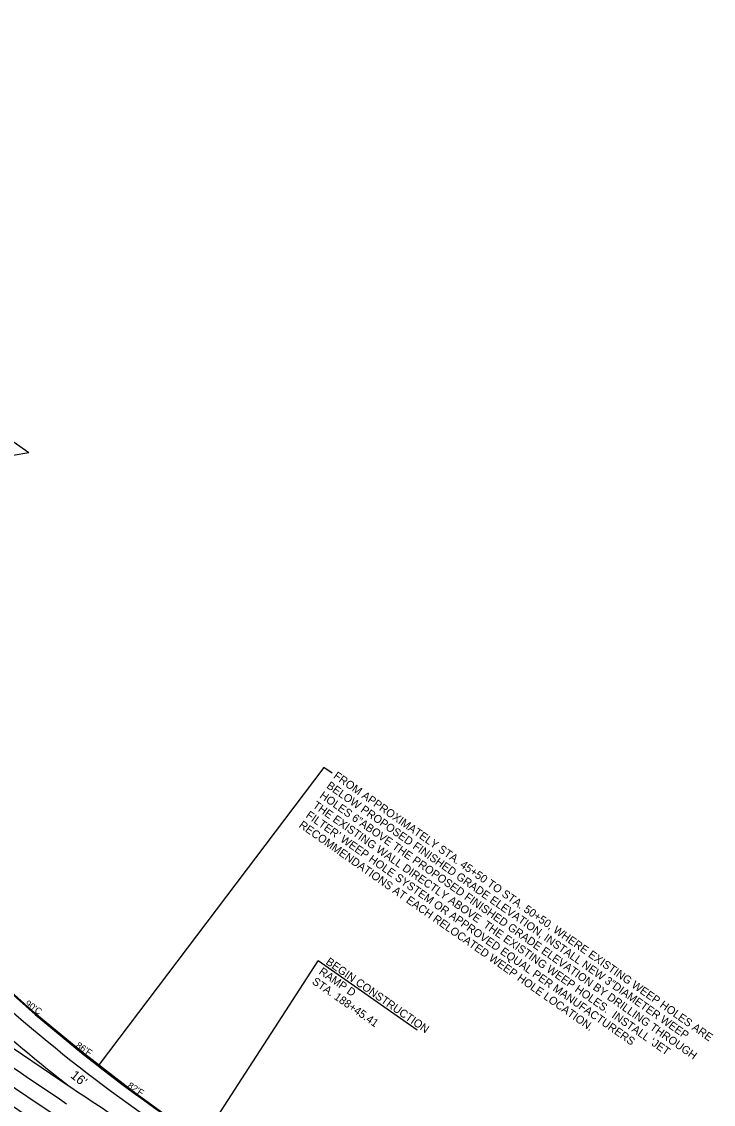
# Model space of a CAD drawing. Extents: x 1966090 to 1975830, y 788086 to 801233.
# Drawn here: x 1972167 to 1972685, y 795066 to 795878 of the extents above; entities that cross this region are included whole.
import ezdxf

# ---------------------------------------------------------------- set-up
doc = ezdxf.new("R2010")
doc.units = 0
for name, color, linetype in [('BR_PROPOSED_DRAINAGE', 7, 'Continuous'), ('RD_EX_Driveway_txCode', 7, 'Continuous'), ('RD_EX_RW_TX', 7, 'Continuous'), ('RD_EX_SU_Gas', 7, 'Continuous'), ('RD_PD_PaveShd', 7, 'Continuous'), ('RD_Sketch6', 7, 'Continuous'), ('RD_Sketch8', 7, 'Continuous')]:
    doc.layers.add(name, color=color, linetype=linetype)

msp = doc.modelspace()

# ---------------------------------------------------------------- linework, layer by layer
at = {"layer": 'BR_PROPOSED_DRAINAGE'}
for p, q in [((1972137.41, 795169.72), (1972174.03, 795136.99)), ((1972174.03, 795136.99), (1972211.9, 795105.82)), ((1972211.9, 795105.82), (1972250.63, 795075.75)), ((1972250.63, 795075.75), (1972290.37, 795047.06))]:
    msp.add_line(p, q, dxfattribs=at)
at = {"layer": 'RD_EX_SU_Gas'}
for radius, start, end in [(3784.72, 216.39766, 236.97136), (3796.72, 216.39766, 236.97136), (3842.72, 216.39766, 244.09898), (3854.72, 216.39766, 243.9112), (3866.72, 216.9932, 243.9112), (3772.72, 227.89927, 236.25939), (3760.72, 236.17378, 236.97136)]:
    msp.add_arc((1974296, 798203.94), radius, start, end, dxfattribs=at)
at = {"layer": 'RD_PD_PaveShd'}
for centre, radius, start, end in [((1974296, 798203.94), 3820.72, 222.66541, 243.9112), ((1974296, 798203.94), 3818.72, 222.66592, 243.9112), ((1972996.53, 796085.43), 1256, 225.41147, 239.13377)]:
    msp.add_arc(centre, radius, start, end, dxfattribs=at)
at = {"layer": 'RD_Sketch6'}
for p, q in [((1972010.36, 795667.58), (1972172.12, 795554.73)), ((1971678.64, 795470.16), (1972172.12, 795554.73)), ((1972393.25, 795318.7), (1972224.93, 795096.17)), ((1972399.53, 795314.29), (1972393.25, 795318.7)), ((1972297.24, 795032.17), (1972388.83, 795173.88)), ((1972463.15, 795121.69), (1972388.83, 795173.88))]:
    msp.add_line(p, q, dxfattribs=at)
at = {"layer": 'RD_Sketch8'}
for centre, radius, start, end in [((1974296, 798203.94), 3808.72, 216.39766, 236.97136), ((1974296, 798203.94), 3830.72, 216.39766, 243.9112), ((1974296, 798203.94), 3878.72, 216.39766, 241.30888), ((1974296, 798203.94), 3760.72, 227.90275, 236.17378), ((1973117.1, 796675.98), 1984, 226.17145, 243.9112), ((1972948.57, 796040.02), 1200, 225.41147, 237.12717), ((1972948.57, 796040.02), 1216, 225.41147, 232.15338)]:
    msp.add_arc(centre, radius, start, end, dxfattribs=at)

# ---------------------------------------------------------------- texts
at = {"layer": 'RD_EX_Driveway_txCode'}
msp.add_text("16'", height=7, rotation=321.43103, dxfattribs=at).set_placement((1972202.86, 795086.84))
at = {"layer": 'RD_EX_RW_TX'}
for s, rotation, p in [("90'C", 325.32136, (1972168.77, 795140.63)), ("86'F", 326.07136, (1972206.9, 795109.19)), ("82'F", 326.82136, (1972245.59, 795079.05))]:
    msp.add_text(s, height=5, rotation=rotation, dxfattribs=at).set_placement(p)
at = {"layer": 'RD_Sketch6'}
for s, height, rotation, p in [('FROM APPROXIMATELY STA. 45+50 TO STA. 50+50, WHERE EXISTING WEEP HOLES ARE ', 6, 324.92357, (1972399.86, 795311.16)), ('BELOW PROPOSED FINISHED GRADE ELEVATION, INSTALL NEW 3”DIAMETER WEEP ', 6, 324.92357, (1972394.69, 795303.79)), ('HOLES 6”ABOVE THE PROPOSED FINISHED GRADE ELEVATION BY DRILLING THROUGH ', 6, 324.92357, (1972389.52, 795296.43)), ('THE EXISTING WALL DIRECTLY ABOVE  THE EXISTING WEEP HOLES.  INSTALL ‘JET ', 6, 324.92357, (1972384.35, 795289.06)), ('FILTER’ WEEP HOLE SYSTEM OR APPROVED EQUAL PER MANUFACTURERS ', 6, 324.92357, (1972379.17, 795281.7)), ('RECOMMENDATIONS AT EACH RELOCATED WEEP HOLE LOCATION.', 6, 324.92357, (1972374, 795274.33)), ('BEGIN CONSTRUCTION', 5.9996, 325.08507, (1972394.12, 795171.78)), ('RAMP D', 6, 325.08507, (1972388.97, 795164.4)), ('STA. 188+45.41', 5.9996, 325.08507, (1972383.82, 795157.02))]:
    msp.add_text(s, height=height, rotation=rotation, dxfattribs=at).set_placement(p)

doc.saveas('drawing.dxf')
